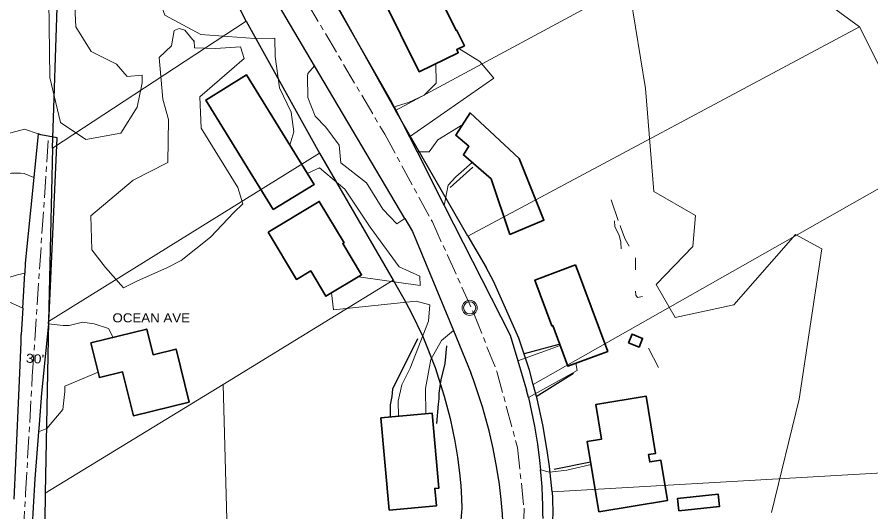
# Model space of a CAD drawing. Extents: x -861682 to -858969, y -1797841 to -1795153.
# Drawn here: x -860350 to -859783, y -1796143 to -1795814 of the extents above; entities that cross this region are included whole.
import ezdxf

# ---------------------------------------------------------------- set-up
doc = ezdxf.new("R2010")
doc.units = 0
doc.header["$LTSCALE"] = 2.4
doc.linetypes.add('LONG_DASH_SHORT_DASH', pattern=[9.9, 6, -1.2, 1.5, -1.2])
doc.linetypes.add('LONG_DASHED', pattern=[7.5, 6, -1.5])
for name, color, linetype, lineweight in [('10', 7, 'Continuous', 25), ('11', 7, 'Continuous', 13), ('12', 7, 'Continuous', 35), ('14', 7, 'Continuous', 25), ('18', 7, 'Continuous', 13), ('30', 7, 'Continuous', 13), ('32', 7, 'LONG_DASH_SHORT_DASH', 13), ('36', 7, 'Continuous', 13), ('42', 7, 'Continuous', 25), ('46', 7, 'Continuous', 13), ('52', 7, 'LONG_DASHED', 13)]:
    doc.layers.add(name, color=color, linetype=linetype, lineweight=lineweight)
doc.layers.add('43', color=7, linetype='Continuous')

msp = doc.modelspace()

# ---------------------------------------------------------------- linework, layer by layer
at = {"layer": '10'}
for p, q in [((-860099.377, -1795873.799), (-860089.266, -1795893.733)), ((-860335.906, -1795891.78), (-860338.779, -1795920.831)), ((-860089.266, -1795893.733), (-860084.185, -1795903.752)), ((-860084.185, -1795903.752), (-860066.071, -1795939.467)), ((-860346.068, -1796007.534), (-860344.775, -1795984.4)), ((-860346.068, -1796007.534), (-860347.053, -1796025.144)), ((-860329.066, -1796017.997), (-860328.496, -1796012.458)), ((-860060.06, -1796022.443), (-860048.39, -1796050.652)), ((-860017.297, -1796042.567), (-860011.428, -1796062.144)), ((-860010.212, -1796066.993), (-860011.428, -1796062.144))]:
    msp.add_line(p, q, dxfattribs=at)
for points in [[(-860099.377, -1795873.799), (-860101.725, -1795869.17), (-860162.861, -1795761.969)], [(-860092.401, -1795947.984), (-860152.258, -1795846.506), (-860179.156, -1795800.905)], [(-860328.496, -1796012.458), (-860323.148, -1795894.502), (-860334.171, -1795892.356), (-860335.906, -1795891.78)], [(-860338.779, -1795920.831), (-860344.397, -1795977.627), (-860344.775, -1795984.4)], [(-860066.071, -1795939.467), (-860022.381, -1796025.614), (-860017.297, -1796042.567)], [(-860092.401, -1795947.984), (-860087.255, -1795956.71), (-860060.06, -1796022.443)], [(-860329.066, -1796017.997), (-860331.092, -1796037.671), (-860333.549, -1796064.005), (-860335.314, -1796084.868), (-860335.676, -1796089.767)], [(-860351.797, -1796134.634), (-860350.709, -1796110.669), (-860348.324, -1796055.621), (-860347.259, -1796030.14), (-860347.053, -1796025.144)], [(-860026.826, -1796183.149), (-860026.784, -1796182.074), (-860026.672, -1796178.744), (-860026.561, -1796173.235), (-860026.542, -1796171.031), (-860026.537, -1796168.827), (-860026.558, -1796165.521), (-860026.666, -1796160.012), (-860026.915, -1796153.405), (-860027.452, -1796144.606), (-860028.334, -1796134.728), (-860029.51, -1796124.88), (-860031.161, -1796113.985), (-860033.615, -1796100.991), (-860036.318, -1796089.175), (-860040.692, -1796073.236), (-860046.644, -1796055.336), (-860048.39, -1796050.652)], [(-860010.212, -1796066.993), (-860006.162, -1796085.98), (-860004.182, -1796097.938), (-860002.751, -1796108.864), (-860002.141, -1796114.955)], [(-860335.676, -1796089.767), (-860337.997, -1796121.135), (-860339.19, -1796139.831), (-860340.577, -1796164.709), (-860340.829, -1796169.703)], [(-860000.524, -1796147.349), (-860000.544, -1796144.044), (-860000.65, -1796138.535), (-860000.844, -1796133.028), (-860001.194, -1796126.426), (-860001.764, -1796118.733), (-860002.141, -1796114.955)]]:
    msp.add_lwpolyline(points, dxfattribs=at)
at = {"layer": '11'}
msp.add_line((-859989.204, -1796032.384), (-860017.297, -1796042.567), dxfattribs=at)
for points in [[(-860256.318, -1795799.851), (-860251.792, -1795812.826), (-860227.813, -1795825.849), (-860191.874, -1795828.371), (-860178.642, -1795828.255), (-860178.537, -1795840.305), (-860175.518, -1795861.309), (-860167.817, -1795877.31), (-860166.047, -1795890.527), (-860168.708, -1795899.351)], [(-860056.533, -1795835.172), (-860042.402, -1795843.605), (-860033.088, -1795854.866), (-860089.266, -1795893.733)], [(-860071.689, -1795845.132), (-860071.577, -1795858.038), (-860079.54, -1795866.142), (-860089.895, -1795870.958), (-860099.377, -1795873.799)], [(-860092.401, -1795947.984), (-860097.697, -1795951.602), (-860106.998, -1795941.759), (-860117.784, -1795924.368), (-860134.913, -1795911.049), (-860135.962, -1795899.243), (-860144.809, -1795887.269), (-860151.962, -1795880.007), (-860156.796, -1795867.525), (-860156.918, -1795853.585), (-860156.699, -1795851.693), (-860152.258, -1795846.506)], [(-860053.845, -1795885.47), (-860070.301, -1795895.834), (-860076.14, -1795903.683), (-860084.185, -1795903.752)], [(-860382.998, -1795900.616), (-860364.271, -1795893.679), (-860344.937, -1795888.785), (-860335.906, -1795891.78)], [(-860047.653, -1795910.749), (-860058.509, -1795920.306), (-860063.423, -1795925.783), (-860066.071, -1795939.467)], [(-860377.503, -1795927.042), (-860374.63, -1795924.961), (-860362.868, -1795918.951), (-860353.662, -1795917.925), (-860347.518, -1795917.872), (-860345.154, -1795918.087), (-860338.779, -1795920.831)], [(-860157.16, -1795918.124), (-860149.061, -1795914.48), (-860132.161, -1795928.51), (-860115.399, -1795953.884), (-860096.029, -1795980.18), (-860082.27, -1795986.44), (-860082.216, -1795992.583), (-860123.121, -1795986.781)], [(-860511.432, -1795999.454), (-860499.637, -1796032.386), (-860472.127, -1796016.787), (-860456.099, -1796012.157), (-860436.312, -1796005.132), (-860411.805, -1795997.356), (-860385.86, -1795991.931), (-860369.088, -1795991.312), (-860349.527, -1795985.469), (-860344.775, -1795984.4)], [(-860140.937, -1795997.436), (-860139.731, -1796008.682), (-860084.724, -1796003.002), (-860075.723, -1796005.523), (-860076.575, -1796016.164), (-860088.825, -1796047.462), (-860094.399, -1796058.616), (-860096.667, -1796069.506), (-860096.58, -1796079.436)], [(-860494.603, -1796096.087), (-860491.039, -1796069.882), (-860487.797, -1796062.292), (-860482.727, -1796047.598), (-860471.744, -1796033.56), (-860459.053, -1796025.652), (-860443.995, -1796018.195), (-860361.431, -1796002.351), (-860357.886, -1796002.32), (-860346.068, -1796007.534)], [(-860286.008, -1796027.036), (-860289.197, -1796021.095), (-860298.675, -1796018.106), (-860306.482, -1796016.993), (-860315.206, -1796019.196), (-860319.223, -1796019.231), (-860329.066, -1796017.997)], [(-860078.399, -1796077.805), (-860078.546, -1796061.077), (-860074.934, -1796041.669), (-860067.955, -1796029.085), (-860060.06, -1796022.443)], [(-859978.796, -1796044.264), (-859977.752, -1796049.09), (-860010.212, -1796066.993)], [(-860296.056, -1796050.181), (-860318.163, -1796059.392), (-860318.132, -1796062.936), (-860319.444, -1796074.999), (-860330.204, -1796087.616), (-860335.676, -1796089.767)], [(-859968.627, -1796111.612), (-859984.735, -1796115.313), (-859996.303, -1796116.595), (-860002.141, -1796114.955)]]:
    msp.add_lwpolyline(points, dxfattribs=at)
at = {"layer": '12'}
for points in [[(-860107.286, -1795800.692), (-860082.748, -1795850.573), (-860056.867, -1795837.841), (-860057.859, -1795835.824), (-860052.695, -1795833.284), (-860057.75, -1795823.007), (-860058.178, -1795823.217), (-860076.614, -1795785.643)], [(-860179.774, -1795942.159), (-860224.598, -1795869.299), (-860197.465, -1795852.607), (-860152.642, -1795925.467)], [(-860022.551, -1795958.632), (-860034.867, -1795921.751), (-860053.357, -1795905.84), (-860049.692, -1795899.999), (-860058.51, -1795892.67), (-860048.955, -1795877.924), (-860016.319, -1795908.121), (-859999.893, -1795949.092)], [(-860183.188, -1795957.075), (-860149.103, -1795936.692), (-860132.692, -1795964.135), (-860133.513, -1795964.626), (-860121.016, -1795985.522), (-860144.754, -1795999.719), (-860154.839, -1795982.857), (-860164.362, -1795988.553)], [(-859978.839, -1795978.918), (-859957.542, -1796036.388), (-859984.077, -1796046.221), (-859994.088, -1796019.204), (-859994.563, -1796019.38), (-860005.847, -1795988.925)], [(-860235.604, -1796070.011), (-860272.623, -1796079.077), (-860279.755, -1796049.957), (-860295.185, -1796053.736), (-860300.835, -1796030.668), (-860263.715, -1796021.576), (-860259.54, -1796038.62), (-860244.213, -1796034.866)], [(-859943.651, -1796030.596), (-859941.338, -1796024.905), (-859934.35, -1796027.745), (-859936.663, -1796033.436)], [(-859963.463, -1796143.008), (-859917.924, -1796135.522), (-859922.355, -1796108.566), (-859929.67, -1796109.768), (-859930.462, -1796104.947), (-859925.757, -1796104.174), (-859932.015, -1796066.086), (-859965.43, -1796071.576), (-859961.643, -1796094.624), (-859971.164, -1796096.19)], [(-860108.15, -1796080.474), (-860102.651, -1796141.863), (-860071.372, -1796139.061), (-860072.416, -1796127.412), (-860069.64, -1796127.163), (-860074.102, -1796077.42)], [(-859910.303, -1796142.308), (-859883.39, -1796139.473), (-859884.262, -1796131.197), (-859911.175, -1796134.033)]]:
    msp.add_lwpolyline(points, close=True, dxfattribs=at)
at = {"layer": '14'}
for p, q in [((-860047.224, -1795913.827), (-860062.241, -1795927.514)), ((-860012.823, -1796037.817), (-859989.721, -1796031.472)), ((-860005.111, -1796066.239), (-859980.198, -1796050.898)), ((-859968.95, -1796109.976), (-859993.009, -1796114.912))]:
    msp.add_line(p, q, dxfattribs=at)
for points in [[(-860083.796, -1796028.041), (-860100.517, -1796061.505), (-860100.948, -1796066.235), (-860102.08, -1796071.916), (-860102.01, -1796079.923)], [(-860064.617, -1796032.599), (-860065.695, -1796044.423), (-860068.435, -1796055.317), (-860069.777, -1796064.071), (-860069.744, -1796067.852), (-860070.185, -1796071.4), (-860071.255, -1796084.169)]]:
    msp.add_lwpolyline(points, dxfattribs=at)
at = {"layer": '18'}
for points in [[(-859848.857, -1796143.423), (-859830.375, -1796068.119), (-859815.416, -1795968.272), (-859832.749, -1795958.736), (-859873.693, -1796005.407), (-859912.844, -1796013.783), (-859925.323, -1795991.917), (-859900.969, -1795966.657), (-859899.258, -1795946.084), (-859926.809, -1795930.021), (-859932.369, -1795861.544), (-859942.357, -1795800.194), (-859992.827, -1795784.331), (-859993.663, -1795769.689), (-860006.382, -1795747.353), (-860037.691, -1795706.748), (-860081.491, -1795642.86), (-860097.65, -1795605.431), (-860097.883, -1795578.733), (-860086.247, -1795531.136), (-860086.234, -1795505.617), (-860108.054, -1795442.246)], [(-860312.494, -1795788.782), (-860310.798, -1795820.667), (-860300.729, -1795837.12), (-860283.879, -1795845.479), (-860276.719, -1795853.687), (-860266.801, -1795852.892), (-860266.758, -1795857.853), (-860270.162, -1795873.951), (-860280.88, -1795891.294), (-860304.236, -1795895.515), (-860321.111, -1795884.321), (-860328.225, -1795854.373), (-860328.673, -1795803.101)], [(-860291.204, -1795980.704), (-860300.286, -1795968.969), (-860300.957, -1795946.29), (-860272.808, -1795922.651), (-860249.754, -1795910.871), (-860249.295, -1795882.275), (-860252.957, -1795868.839), (-860255.563, -1795840.979), (-860247.36, -1795833.345), (-860245.558, -1795823.169), (-860242.196, -1795821.67), (-860238.416, -1795822.815), (-860232.241, -1795830.467)], [(-860232.28, -1795829.824), (-860231.989, -1795834.629), (-860218.045, -1795834.98), (-860201.514, -1795833.89), (-860199.083, -1795841.667), (-860207.291, -1795848.827), (-860228.397, -1795867.206), (-860227.506, -1795887.992), (-860203.295, -1795927.478), (-860199.892, -1795938.318), (-860205.986, -1795944.043), (-860221.438, -1795960.482), (-860240.915, -1795976.011), (-860249.854, -1795980.579), (-860270.332, -1795989.737), (-860279.273, -1795994.069), (-860291.204, -1795980.704)]]:
    msp.add_lwpolyline(points, dxfattribs=at)
at = {"layer": '30'}
for p, q in [((-859877.343, -1795756.894), (-860098.4, -1795876.369)), ((-859790.315, -1795820.662), (-859877.343, -1795756.894)), ((-860197.805, -1795816.843), (-860326.268, -1795901.28)), ((-859790.315, -1795820.662), (-860050.464, -1795959.795)), ((-859790.315, -1795820.662), (-859745.262, -1795910.868)), ((-860148.955, -1795904.538), (-860328.968, -1796016.393)), ((-860331.139, -1796130.629), (-860213.051, -1796058.32))]:
    msp.add_line(p, q, dxfattribs=at)
for points in [[(-860006.992, -1796058.327), (-859755.585, -1795915.677), (-859745.262, -1795910.868)], [(-860100.109, -1795989.121), (-860213.051, -1796058.32), (-860205.797, -1796319.285)], [(-859994.502, -1796129.729), (-859724.754, -1796114.194), (-859643.077, -1796117.35)]]:
    msp.add_lwpolyline(points, dxfattribs=at)
at = {"layer": '32'}
for points in [[(-860274.26, -1795653.513), (-860250.487, -1795671.004), (-860229.924, -1795692.424), (-860208.503, -1795727.553), (-860157.095, -1795804.667), (-860105.686, -1795892.062), (-860073.984, -1795950.325), (-860046.566, -1796011.159), (-860031.143, -1796049.715), (-860017.434, -1796100.268), (-860013.15, -1796140.538), (-860014.007, -1796179.951), (-860021.718, -1796250.638), (-860037.649, -1796318.494)], [(-860350.575, -1797816.671), (-860352.537, -1797784.701), (-860351.442, -1797711.343), (-860351.99, -1797541.086), (-860353.632, -1797469.37), (-860356.368, -1797360.975), (-860359.105, -1797223.017), (-860359.105, -1797136.52), (-860357.161, -1797049.888), (-860352.185, -1796782.715), (-860350.693, -1796661.317), (-860345.219, -1796479.719), (-860348.204, -1796383.696), (-860339.249, -1796324.987), (-860344.224, -1796287.673), (-860347.707, -1796239.412), (-860347.209, -1796180.704), (-860344.224, -1796130.951), (-860339.746, -1796052.839), (-860328.991, -1795893.364)]]:
    msp.add_lwpolyline(points, dxfattribs=at)
at = {"layer": '36'}
for radius in [5, 4]:
    msp.add_circle((-860049.241, -1796007.418), radius, dxfattribs=at)
at = {"layer": '42'}
for p, q in [((-860326.268, -1795901.28), (-860317.813, -1795647.116)), ((-860197.805, -1795816.843), (-860250.84, -1795711.923)), ((-860142.962, -1795796.48), (-860098.4, -1795876.369)), ((-860197.805, -1795816.843), (-860148.955, -1795904.538)), ((-860050.464, -1795959.795), (-860098.4, -1795876.369)), ((-860326.268, -1795901.28), (-860328.968, -1796016.393)), ((-860148.955, -1795904.538), (-860100.109, -1795989.121)), ((-860050.464, -1795959.795), (-860038.233, -1795980.693)), ((-860100.109, -1795989.121), (-860092.863, -1796001.383)), ((-860328.968, -1796016.393), (-860331.139, -1796130.629))]:
    msp.add_line(p, q, dxfattribs=at)
for points in [[(-860006.992, -1796058.327), (-860009.553, -1796048.768), (-860016.634, -1796027.652), (-860033.379, -1795989.749), (-860038.233, -1795980.693)], [(-860092.863, -1796001.383), (-860088.006, -1796010.415), (-860080.373, -1796026.388), (-860072.135, -1796047.143), (-860066.098, -1796066.137), (-860062.275, -1796081.023), (-860059.18, -1796095.926), (-860057.393, -1796106.542), (-860055.963, -1796117.114), (-860055.293, -1796123.444), (-860055.107, -1796125.554), (-860054.604, -1796134.026), (-860054.556, -1796140.462), (-860055.663, -1796153.755), (-860078.293, -1796275.127)], [(-859994.502, -1796129.729), (-859994.852, -1796125.514), (-859995.26, -1796121.295), (-859996.226, -1796112.834), (-859997.69, -1796102.204), (-860000.629, -1796085.105), (-860004.356, -1796067.972), (-860006.992, -1796058.327)], [(-860331.139, -1796130.629), (-860333.796, -1796350.4), (-860205.004, -1796329.448), (-860208.571, -1796319.923), (-860205.797, -1796319.285)], [(-859994.502, -1796129.729), (-859994.219, -1796133.946), (-859993.927, -1796144.571), (-859995.098, -1796160.007)]]:
    msp.add_lwpolyline(points, dxfattribs=at)
at = {"layer": '52'}
msp.add_line((-859930.387, -1796034.261), (-859922.696, -1796049.081), dxfattribs=at)
for points in [[(-859955.35, -1795935.709), (-859949.05, -1795953.613), (-859945.906, -1795961.856), (-859943.267, -1795966.322)], [(-859953.101, -1795949.631), (-859952.83, -1795953.646), (-859949.947, -1795959.055), (-859948.725, -1795963.77), (-859948.685, -1795968.26)], [(-859939.183, -1795974.084), (-859939.156, -1795977.156), (-859939.123, -1795980.936), (-859939.112, -1795982.118)], [(-859938.989, -1795996.294), (-859938.966, -1795998.893), (-859937.77, -1796000.537), (-859934.468, -1795999.799)]]:
    msp.add_lwpolyline(points, dxfattribs=at)

# ---------------------------------------------------------------- texts
at = {"layer": '43', "width": 1.15}
msp.add_text("30'", height=6, rotation=356.179, dxfattribs=at).set_placement((-860344.124, -1796043.787))
at = {"layer": '46', "width": 1.1}
msp.add_text('OCEAN AVE', height=6, dxfattribs=at).set_placement((-860286.503, -1796017.051))

doc.saveas('drawing.dxf')
